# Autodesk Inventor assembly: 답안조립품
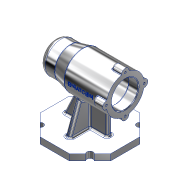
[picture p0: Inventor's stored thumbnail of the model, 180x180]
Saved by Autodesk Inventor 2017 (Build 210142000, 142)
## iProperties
Created: 2019-12
Part Number: 답안조립품
Document SubType Name: Assembly
Designer: 5-14-le
Author: 5-14-le
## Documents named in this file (2)
- C:\Users\5-14-le\Desktop\491204V1011\답안조립품.iam
- C:\Users\5-14-le\Desktop\491204V1011\본체.ipt
